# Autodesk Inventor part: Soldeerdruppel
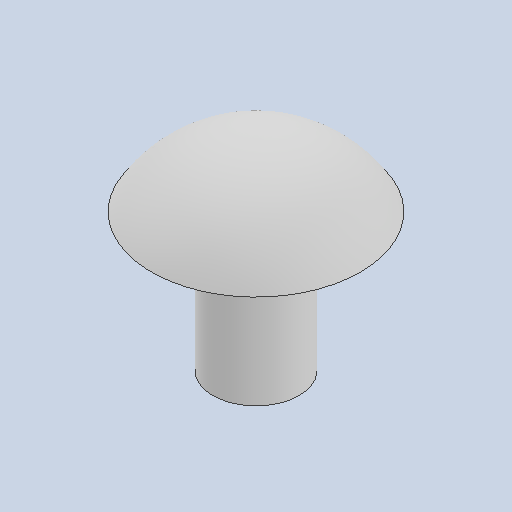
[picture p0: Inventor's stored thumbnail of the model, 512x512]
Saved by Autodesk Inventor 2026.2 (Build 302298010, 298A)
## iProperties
Created: 2023-02
Part Number: Soldeerdruppel
Material: Generic
Document SubType Name: Modeling
Designer: mel
Density: 1 g/cm^3
Appearance: Par défaut
Author: mel
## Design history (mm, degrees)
feature "Solid1"
node "Solide1"
